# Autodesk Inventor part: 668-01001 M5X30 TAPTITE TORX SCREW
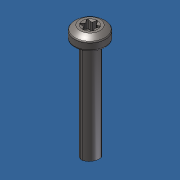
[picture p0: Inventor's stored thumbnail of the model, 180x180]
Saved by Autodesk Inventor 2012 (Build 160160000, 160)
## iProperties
Created: 2013-10
Part Number: 668-01001 M5X30 TAPTITE TORX SCREW
Material: Default
Document SubType Name: Modeling
Designer: Admin
Density: 1 g/cm^3
Author: Admin
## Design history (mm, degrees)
node "668-01001 M5X30 TAPTITE TORX SCREW1"
node "Base1"
body "Solid1"
